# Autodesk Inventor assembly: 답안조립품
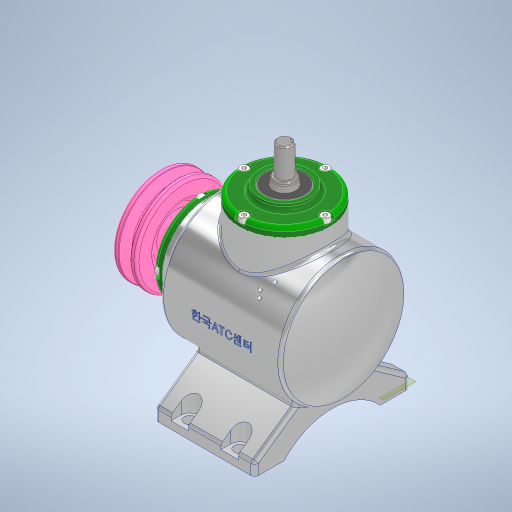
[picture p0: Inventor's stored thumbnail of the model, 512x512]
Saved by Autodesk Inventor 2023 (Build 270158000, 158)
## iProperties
Created: 2023-12
Part Number: 답안조립품
Document SubType Name: Assembly
Designer: asung
Author: asung
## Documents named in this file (17)
- C:\Users\asung\Desktop\731210V1007\731210V1007\답안조립품.iam
- C:\Users\asung\Desktop\731210V1007\본체.ipt
- C:\Users\asung\Desktop\731210V1007\731210V1007\커버.ipt
- C:\Users\asung\Desktop\731210V1007\731210V1007\베어링 6203.ipt
- C:\Users\asung\Desktop\731210V1007\731210V1007\오일실 17 x 32 x 8.ipt
- C:\Users\asung\Desktop\731210V1007\731210V1007\메인 축.ipt
- 메인 축.ipt
- C:\Users\asung\Desktop\731210V1007\731210V1007\서브 축.ipt
- 서브 축.ipt
- C:\Users\asung\Desktop\731210V1007\731210V1007\키 5 x 5 x 14.ipt
- C:\Users\asung\Desktop\731210V1007\731210V1007\키 4 x 4 x 14.ipt
- C:\Users\asung\Desktop\731210V1007\731210V1007\서브 베벨기어.ipt
- C:\Users\asung\Desktop\731210V1007\731210V1007\메인 베벨기어.ipt
- C:\Users\asung\Desktop\731210V1007\731210V1007\볼트 M4 x 10.ipt
- C:\Users\asung\Desktop\731210V1007\731210V1007\V-벨트풀리.ipt
- C:\Users\asung\Desktop\731210V1007\731210V1007\와셔 4 x 16.ipt
- C:\Users\asung\Desktop\731210V1007\731210V1007\육각볼트 M4 x 8.ipt
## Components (1 placed, 1 different names)
1. V-벨트풀리:1
